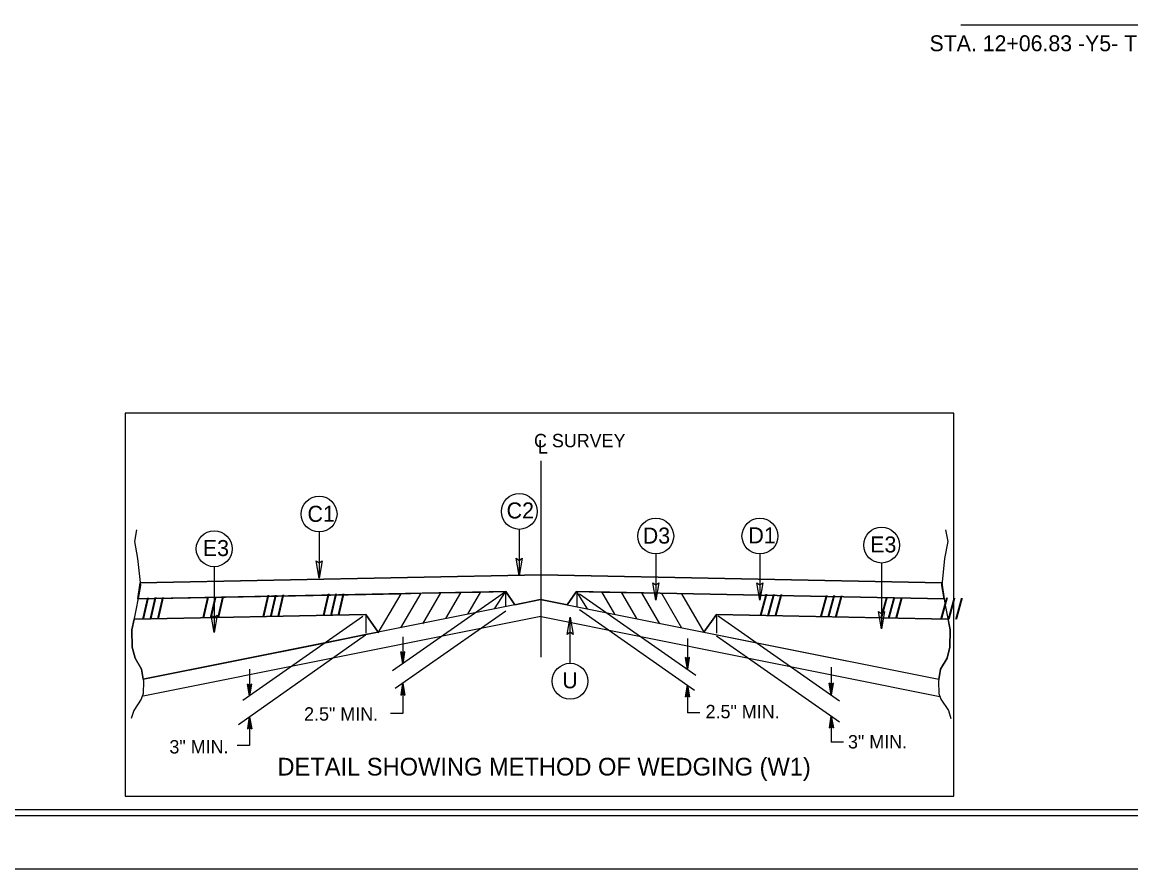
# Model space of a CAD drawing. Extents: x 2176156 to 2177167, y 76401 to 76644.
# Drawn here: x 2176720.1 to 2176795, y 76454.5 to 76511.6 of the extents above; entities that cross this region are included whole.
import ezdxf

# ---------------------------------------------------------------- set-up
doc = ezdxf.new("R2010")
doc.units = 0
for name, color, linetype in [('Exist Other Culture Fence Line', 7, 'Continuous'), ('Exist Utilities Water Fire Hydrant CELL', 7, 'Continuous'), ('Exist Vegetation Hedge Row', 7, 'Continuous'), ('Exist Vegetation Shrub CELL', 7, 'Continuous'), ('Exist Vegetation Woods Line', 7, 'Continuous'), ('Model Boundary Lines', 7, 'Continuous'), ('Model Boundary Lines Text', 7, 'Continuous'), ('Old_Level_1', 7, 'Continuous'), ('Prop North Arrow NAD83 for Plan Sheets CELL', 7, 'Continuous'), ('Scratch_Level_0', 7, 'Continuous'), ('Sheet Cutting Line CELL', 7, 'Continuous'), ('Sheet Data Field CELL', 7, 'Continuous'), ('Sheet Plot Border Outside CELL', 7, 'Continuous'), ('Sheet Sticker Exception Certification CELL', 7, 'Continuous')]:
    doc.layers.add(name, color=color, linetype=linetype)

msp = doc.modelspace()

# ---------------------------------------------------------------- linework, layer by layer
at = {"layer": 'Exist Other Culture Fence Line'}
msp.add_lwpolyline([(2176727.086, 76459.386), (2176783.012, 76459.386), (2176783.012, 76485.213), (2176727.086, 76485.213)], close=True, dxfattribs=at)
at = {"layer": 'Exist Utilities Water Fire Hydrant CELL'}
for p, q in [((2176727.938, 76472.689), (2176728.092, 76473.776)), ((2176755.147, 76474.316), (2176728.092, 76473.776)), ((2176728.092, 76473.776), (2176755.147, 76474.316)), ((2176755.147, 76474.316), (2176782.204, 76473.776)), ((2176755.15, 76474.316), (2176782.204, 76473.776)), ((2176782.204, 76473.776), (2176782.36, 76472.689)), ((2176752.774, 76473.185), (2176727.938, 76472.689)), ((2176752.774, 76473.185), (2176727.938, 76472.689)), ((2176745.679, 76473.043), (2176744.141, 76470.408)), ((2176752.743, 76473.165), (2176745.121, 76467.826)), ((2176747.028, 76473.071), (2176745.668, 76470.734)), ((2176748.365, 76473.097), (2176747.144, 76471.003)), ((2176749.712, 76473.094), (2176748.699, 76471.36)), ((2176751.069, 76473.163), (2176750.187, 76471.65)), ((2176752.005, 76472.028), (2176752.739, 76473.175)), ((2176752.739, 76473.175), (2176752.739, 76472.232)), ((2176753.382, 76472.294), (2176752.774, 76473.185)), ((2176752.774, 76473.156), (2176753.382, 76472.294)), ((2176757.541, 76473.185), (2176756.914, 76472.294)), ((2176757.541, 76473.185), (2176756.914, 76472.294)), ((2176757.502, 76473.165), (2176757.54, 76473.163)), ((2176757.541, 76473.185), (2176782.36, 76472.689)), ((2176782.36, 76472.689), (2176757.541, 76473.185)), ((2176758.291, 76472.028), (2176757.557, 76473.175)), ((2176757.557, 76473.175), (2176757.557, 76472.137)), ((2176757.748, 76473.041), (2176765.602, 76467.541)), ((2176759.226, 76473.163), (2176760.11, 76471.65)), ((2176760.584, 76473.094), (2176761.597, 76471.36)), ((2176761.931, 76473.097), (2176763.153, 76471.003)), ((2176763.268, 76473.071), (2176764.629, 76470.734)), ((2176764.619, 76473.043), (2176766.133, 76470.447)), ((2176755.188, 76472.653), (2176728.295, 76467.273)), ((2176755.108, 76472.653), (2176753.382, 76472.294)), ((2176755.108, 76472.653), (2176782.001, 76467.273)), ((2176756.914, 76472.294), (2176755.108, 76472.653)), ((2176743.312, 76471.639), (2176727.675, 76471.326)), ((2176727.675, 76471.326), (2176743.312, 76471.639)), ((2176755.137, 76471.495), (2176728.286, 76466.124)), ((2176743.128, 76471.51), (2176735.009, 76465.825)), ((2176744.163, 76470.444), (2176743.312, 76471.639)), ((2176743.312, 76471.639), (2176743.312, 76470.377)), ((2176743.312, 76471.639), (2176744.161, 76470.447)), ((2176752.761, 76471.86), (2176745.302, 76466.638)), ((2176755.158, 76471.495), (2176782.072, 76466.111)), ((2176757.737, 76471.972), (2176765.514, 76466.527)), ((2176766.984, 76471.639), (2176766.133, 76470.447)), ((2176766.135, 76470.447), (2176766.984, 76471.639)), ((2176766.984, 76471.639), (2176782.622, 76471.326)), ((2176766.984, 76471.639), (2176766.984, 76470.371)), ((2176778.136, 76471.416), (2176766.984, 76471.639)), ((2176767.11, 76471.551), (2176775.3, 76465.816)), ((2176782.622, 76471.326), (2176778.136, 76471.416)), ((2176743.305, 76470.232), (2176734.722, 76464.192)), ((2176743.312, 76470.277), (2176740.589, 76469.732)), ((2176744.161, 76470.447), (2176743.312, 76470.277)), ((2176745.815, 76470.127), (2176745.815, 76468.313)), ((2176765.028, 76470.022), (2176765.028, 76467.943)), ((2176766.133, 76470.447), (2176769.708, 76469.732)), ((2176766.984, 76470.206), (2176775.286, 76464.391)), ((2176740.589, 76469.732), (2176728.295, 76467.273)), ((2176769.708, 76469.732), (2176782.001, 76467.273)), ((2176745.815, 76468.313), (2176745.674, 76469.108)), ((2176745.815, 76469.005), (2176745.674, 76469.108)), ((2176745.815, 76468.313), (2176745.694, 76469.093)), ((2176745.714, 76469.078), (2176745.815, 76468.313)), ((2176745.815, 76468.313), (2176745.734, 76469.064)), ((2176745.755, 76469.049), (2176745.815, 76468.313)), ((2176745.815, 76468.313), (2176745.775, 76469.035)), ((2176745.795, 76469.02), (2176745.815, 76468.313)), ((2176745.815, 76468.313), (2176745.956, 76469.108)), ((2176745.956, 76469.108), (2176745.815, 76469.005)), ((2176745.936, 76469.093), (2176745.815, 76468.313)), ((2176745.815, 76468.313), (2176745.914, 76469.078)), ((2176745.894, 76469.064), (2176745.815, 76468.313)), ((2176745.815, 76468.313), (2176745.874, 76469.049)), ((2176745.855, 76469.035), (2176745.815, 76468.313)), ((2176745.815, 76468.313), (2176745.835, 76469.02)), ((2176745.815, 76469.005), (2176745.815, 76468.313)), ((2176765.028, 76467.943), (2176764.888, 76468.739)), ((2176765.028, 76468.636), (2176764.888, 76468.739)), ((2176765.028, 76467.943), (2176764.908, 76468.724)), ((2176764.928, 76468.709), (2176765.028, 76467.943)), ((2176765.028, 76467.943), (2176764.948, 76468.694)), ((2176764.967, 76468.679), (2176765.028, 76467.943)), ((2176765.028, 76467.943), (2176764.987, 76468.666)), ((2176765.007, 76468.651), (2176765.028, 76467.943)), ((2176765.028, 76467.943), (2176765.168, 76468.739)), ((2176765.168, 76468.739), (2176765.028, 76468.636)), ((2176765.147, 76468.724), (2176765.028, 76467.943)), ((2176765.028, 76467.943), (2176765.128, 76468.709)), ((2176765.108, 76468.694), (2176765.028, 76467.943)), ((2176765.028, 76467.943), (2176765.088, 76468.679)), ((2176765.068, 76468.666), (2176765.028, 76467.943)), ((2176765.028, 76467.943), (2176765.048, 76468.651)), ((2176765.028, 76468.636), (2176765.028, 76467.943)), ((2176735.477, 76467.959), (2176735.477, 76466.151)), ((2176774.737, 76468.091), (2176774.737, 76466.211)), ((2176735.477, 76466.151), (2176735.335, 76466.947)), ((2176735.477, 76466.844), (2176735.335, 76466.947)), ((2176735.477, 76466.151), (2176735.355, 76466.933)), ((2176735.377, 76466.917), (2176735.477, 76466.151)), ((2176735.477, 76466.151), (2176735.397, 76466.903)), ((2176735.477, 76466.151), (2176735.617, 76466.947)), ((2176735.617, 76466.947), (2176735.477, 76466.844)), ((2176735.597, 76466.933), (2176735.477, 76466.151)), ((2176735.477, 76466.151), (2176735.577, 76466.917)), ((2176735.557, 76466.903), (2176735.477, 76466.151)), ((2176745.815, 76466.997), (2176745.674, 76466.201)), ((2176745.694, 76466.217), (2176745.815, 76466.997)), ((2176745.815, 76466.997), (2176745.714, 76466.231)), ((2176745.734, 76466.247), (2176745.815, 76466.997)), ((2176745.815, 76466.997), (2176745.755, 76466.261)), ((2176745.775, 76466.274), (2176745.815, 76466.997)), ((2176745.815, 76466.997), (2176745.795, 76466.289)), ((2176745.815, 76466.997), (2176745.815, 76464.955)), ((2176745.815, 76466.997), (2176745.956, 76466.201)), ((2176745.815, 76466.304), (2176745.815, 76466.997)), ((2176745.835, 76466.289), (2176745.815, 76466.997)), ((2176745.815, 76466.997), (2176745.855, 76466.274)), ((2176745.874, 76466.261), (2176745.815, 76466.997)), ((2176745.815, 76466.997), (2176745.894, 76466.247)), ((2176745.914, 76466.231), (2176745.815, 76466.997)), ((2176745.815, 76466.997), (2176745.936, 76466.217)), ((2176774.737, 76466.211), (2176774.596, 76467.006)), ((2176774.737, 76466.903), (2176774.596, 76467.006)), ((2176774.737, 76466.211), (2176774.616, 76466.991)), ((2176774.636, 76466.977), (2176774.737, 76466.211)), ((2176774.737, 76466.211), (2176774.656, 76466.963)), ((2176774.676, 76466.947), (2176774.737, 76466.211)), ((2176774.737, 76466.211), (2176774.696, 76466.933)), ((2176774.716, 76466.917), (2176774.737, 76466.211)), ((2176774.737, 76466.211), (2176774.877, 76467.006)), ((2176774.877, 76467.006), (2176774.737, 76466.903)), ((2176774.856, 76466.991), (2176774.737, 76466.211)), ((2176774.737, 76466.211), (2176774.836, 76466.977)), ((2176774.816, 76466.963), (2176774.737, 76466.211)), ((2176774.737, 76466.211), (2176774.796, 76466.947)), ((2176774.776, 76466.933), (2176774.737, 76466.211)), ((2176774.737, 76466.211), (2176774.757, 76466.917)), ((2176774.737, 76466.903), (2176774.737, 76466.211)), ((2176735.417, 76466.889), (2176735.477, 76466.151)), ((2176735.477, 76466.151), (2176735.437, 76466.874)), ((2176735.457, 76466.859), (2176735.477, 76466.151)), ((2176735.477, 76466.151), (2176735.536, 76466.889)), ((2176735.517, 76466.874), (2176735.477, 76466.151)), ((2176735.477, 76466.151), (2176735.496, 76466.859)), ((2176735.477, 76466.844), (2176735.477, 76466.151)), ((2176745.674, 76466.201), (2176745.815, 76466.304)), ((2176745.815, 76466.304), (2176745.956, 76466.201)), ((2176765.028, 76466.867), (2176764.888, 76466.072)), ((2176764.888, 76466.072), (2176765.028, 76466.175)), ((2176764.908, 76466.087), (2176765.028, 76466.867)), ((2176765.028, 76466.867), (2176764.928, 76466.101)), ((2176764.948, 76466.117), (2176765.028, 76466.867)), ((2176765.028, 76466.867), (2176764.967, 76466.131)), ((2176764.987, 76466.145), (2176765.028, 76466.867)), ((2176765.028, 76466.867), (2176765.007, 76466.16)), ((2176765.028, 76466.867), (2176765.028, 76465.007)), ((2176765.028, 76466.867), (2176765.168, 76466.072)), ((2176765.028, 76466.175), (2176765.028, 76466.867)), ((2176765.048, 76466.16), (2176765.028, 76466.867)), ((2176765.028, 76466.867), (2176765.068, 76466.145)), ((2176765.088, 76466.131), (2176765.028, 76466.867)), ((2176765.028, 76466.867), (2176765.108, 76466.117)), ((2176765.128, 76466.101), (2176765.028, 76466.867)), ((2176765.028, 76466.867), (2176765.147, 76466.087)), ((2176765.028, 76466.175), (2176765.168, 76466.072)), ((2176735.477, 76464.721), (2176735.335, 76463.925)), ((2176735.357, 76463.94), (2176735.477, 76464.721)), ((2176735.477, 76464.721), (2176735.377, 76463.955)), ((2176735.397, 76463.97), (2176735.477, 76464.721)), ((2176735.477, 76464.721), (2176735.417, 76463.985)), ((2176735.437, 76463.999), (2176735.477, 76464.721)), ((2176735.477, 76464.721), (2176735.457, 76464.013)), ((2176735.477, 76464.721), (2176735.477, 76462.787)), ((2176735.477, 76464.721), (2176735.617, 76463.925)), ((2176735.477, 76464.029), (2176735.477, 76464.721)), ((2176735.496, 76464.013), (2176735.477, 76464.721)), ((2176735.477, 76464.721), (2176735.517, 76463.999)), ((2176735.537, 76463.985), (2176735.477, 76464.721)), ((2176735.477, 76464.721), (2176735.557, 76463.97)), ((2176735.577, 76463.955), (2176735.477, 76464.721)), ((2176735.477, 76464.721), (2176735.597, 76463.94)), ((2176745.815, 76464.955), (2176744.98, 76464.955)), ((2176765.863, 76465.007), (2176765.028, 76465.007)), ((2176774.737, 76464.777), (2176774.596, 76463.981)), ((2176774.616, 76463.996), (2176774.737, 76464.777)), ((2176774.737, 76464.777), (2176774.636, 76464.011)), ((2176774.656, 76464.026), (2176774.737, 76464.777)), ((2176774.737, 76464.777), (2176774.676, 76464.04)), ((2176774.696, 76464.055), (2176774.737, 76464.777)), ((2176774.737, 76464.777), (2176774.716, 76464.069)), ((2176774.737, 76464.777), (2176774.737, 76463.03)), ((2176774.737, 76464.777), (2176774.877, 76463.981)), ((2176774.737, 76464.085), (2176774.737, 76464.777)), ((2176774.757, 76464.069), (2176774.737, 76464.777)), ((2176774.737, 76464.777), (2176774.776, 76464.055)), ((2176774.796, 76464.04), (2176774.737, 76464.777)), ((2176774.737, 76464.777), (2176774.816, 76464.026)), ((2176774.836, 76464.011), (2176774.737, 76464.777)), ((2176774.737, 76464.777), (2176774.856, 76463.996)), ((2176735.335, 76463.925), (2176735.477, 76464.029)), ((2176735.477, 76464.029), (2176735.617, 76463.925)), ((2176774.596, 76463.981), (2176774.737, 76464.085)), ((2176774.737, 76464.085), (2176774.877, 76463.981)), ((2176735.477, 76462.787), (2176734.642, 76462.787)), ((2176775.571, 76463.03), (2176774.737, 76463.03))]:
    msp.add_line(p, q, dxfattribs=at)
for points in [[(2176727.841, 76477.347), (2176727.697, 76476.554), (2176727.913, 76475.427), (2176728.104, 76473.603), (2176727.841, 76472.163), (2176727.529, 76470.603), (2176727.553, 76469.426), (2176727.745, 76468.683), (2176728.178, 76467.938), (2176728.321, 76467.123), (2176728.297, 76466.307), (2176728.153, 76465.922), (2176727.65, 76465.154), (2176727.482, 76464.626)], [(2176782.455, 76477.347), (2176782.599, 76476.554), (2176782.383, 76475.427), (2176782.191, 76473.603), (2176782.455, 76472.163), (2176782.767, 76470.603), (2176782.743, 76469.426), (2176782.551, 76468.683), (2176782.119, 76467.938), (2176781.976, 76467.123), (2176781.998, 76466.307), (2176782.143, 76465.922), (2176782.646, 76465.154), (2176782.814, 76464.626)], [(2176728.294, 76467.273), (2176728.178, 76467.938), (2176727.745, 76468.683), (2176727.553, 76469.426), (2176727.529, 76470.603), (2176727.674, 76471.326)], [(2176782.001, 76467.273), (2176782.119, 76467.938), (2176782.551, 76468.683), (2176782.743, 76469.426), (2176782.767, 76470.603), (2176782.622, 76471.326)]]:
    msp.add_lwpolyline(points, dxfattribs=at)
at = {"layer": 'Exist Vegetation Shrub CELL'}
for p, q in [((2176753.679, 76477.383), (2176753.679, 76474.26)), ((2176740.167, 76477.209), (2176740.167, 76474.086)), ((2176762.891, 76475.723), (2176762.891, 76472.6)), ((2176769.92, 76475.723), (2176769.92, 76472.6)), ((2176733.084, 76474.863), (2176733.084, 76470.422)), ((2176778.136, 76475.111), (2176778.136, 76470.67)), ((2176757.106, 76468.345), (2176757.106, 76471.468))]:
    msp.add_line(p, q, dxfattribs=at)
for centre in [(2176740.167, 76478.418), (2176753.679, 76478.592), (2176762.891, 76476.932), (2176769.919, 76476.932), (2176778.136, 76476.319), (2176733.084, 76476.071), (2176757.106, 76467.137)]:
    msp.add_circle(centre, 1.208, dxfattribs=at)
at = {"layer": 'Model Boundary Lines Text'}
msp.add_line((2176783.485, 76511.423), (2176810.807, 76511.423), dxfattribs=at)
at = {"layer": 'Old_Level_1'}
for points in [[(2176740.369, 76475.258), (2176740.167, 76474.086), (2176739.959, 76475.264), (2176740.167, 76475.115)], [(2176740.369, 76475.258), (2176740.167, 76474.086), (2176739.959, 76475.264), (2176740.167, 76475.115)], [(2176753.881, 76475.432), (2176753.679, 76474.26), (2176753.471, 76475.439), (2176753.679, 76475.289)], [(2176753.881, 76475.432), (2176753.679, 76474.26), (2176753.471, 76475.439), (2176753.679, 76475.289)], [(2176763.092, 76473.772), (2176762.891, 76472.6), (2176762.682, 76473.779), (2176762.891, 76473.629)], [(2176763.092, 76473.772), (2176762.891, 76472.6), (2176762.682, 76473.779), (2176762.891, 76473.629)], [(2176770.121, 76473.772), (2176769.92, 76472.6), (2176769.711, 76473.779), (2176769.92, 76473.629)], [(2176770.121, 76473.772), (2176769.92, 76472.6), (2176769.711, 76473.779), (2176769.92, 76473.629)], [(2176733.286, 76471.594), (2176733.084, 76470.422), (2176732.876, 76471.6), (2176733.084, 76471.451)], [(2176733.286, 76471.594), (2176733.084, 76470.422), (2176732.876, 76471.6), (2176733.084, 76471.451)], [(2176756.904, 76470.297), (2176757.106, 76471.468), (2176757.314, 76470.29), (2176757.106, 76470.44)], [(2176756.904, 76470.297), (2176757.106, 76471.468), (2176757.314, 76470.29), (2176757.106, 76470.44)], [(2176778.338, 76471.841), (2176778.136, 76470.67), (2176777.928, 76471.848), (2176778.136, 76471.698)]]:
    msp.add_lwpolyline(points, close=True, dxfattribs=at)
at = {"layer": 'Prop North Arrow NAD83 for Plan Sheets CELL'}
for p, q in [((2176755.148, 76468.754), (2176755.148, 76482.012)), ((2176728.092, 76473.776), (2176728.089, 76473.751)), ((2176755.147, 76474.316), (2176728.092, 76473.776)), ((2176782.207, 76473.755), (2176782.204, 76473.776)), ((2176727.938, 76472.689), (2176745.679, 76473.043)), ((2176745.679, 76473.043), (2176747.028, 76473.07)), ((2176747.028, 76473.07), (2176747.028, 76473.071)), ((2176752.774, 76473.185), (2176753.382, 76472.294)), ((2176757.541, 76473.185), (2176759.233, 76473.151)), ((2176763.268, 76473.071), (2176763.268, 76473.071)), ((2176763.268, 76473.071), (2176764.619, 76473.044)), ((2176764.619, 76473.044), (2176782.359, 76472.689)), ((2176727.942, 76472.718), (2176727.938, 76472.689)), ((2176753.382, 76472.294), (2176755.108, 76472.653)), ((2176743.312, 76471.639), (2176727.675, 76471.326)), ((2176744.161, 76470.447), (2176743.312, 76471.639)), ((2176766.984, 76471.639), (2176766.133, 76470.447)), ((2176778.136, 76471.416), (2176766.984, 76471.639)), ((2176782.622, 76471.326), (2176778.136, 76471.416)), ((2176727.675, 76471.326), (2176727.529, 76470.603)), ((2176769.708, 76469.732), (2176782.001, 76467.273)), ((2176782.119, 76467.938), (2176782.551, 76468.683)), ((2176728.178, 76467.938), (2176728.295, 76467.273)), ((2176782.001, 76467.273), (2176782.119, 76467.938))]:
    msp.add_line(p, q, dxfattribs=at)
for points in [[(2176728.089, 76473.751), (2176728.104, 76473.603), (2176727.942, 76472.718)], [(2176782.204, 76473.776), (2176755.15, 76474.316), (2176755.147, 76474.316)], [(2176782.359, 76472.689), (2176782.191, 76473.603), (2176782.207, 76473.755)], [(2176747.028, 76473.07), (2176748.365, 76473.097), (2176751.062, 76473.151), (2176752.774, 76473.185)], [(2176747.028, 76473.071), (2176747.028, 76473.07)], [(2176756.914, 76472.294), (2176757.527, 76473.164), (2176757.541, 76473.185)], [(2176759.233, 76473.151), (2176761.931, 76473.097), (2176763.268, 76473.071)], [(2176763.268, 76473.071), (2176763.268, 76473.071)], [(2176755.108, 76472.653), (2176755.148, 76472.645), (2176756.914, 76472.294)], [(2176782.551, 76468.683), (2176782.743, 76469.426), (2176782.767, 76470.603), (2176782.622, 76471.326)], [(2176727.529, 76470.603), (2176727.553, 76469.426), (2176727.745, 76468.683), (2176728.178, 76467.938)], [(2176728.295, 76467.273), (2176740.589, 76469.732), (2176740.589, 76469.732), (2176743.312, 76470.277)], [(2176743.312, 76470.277), (2176744.118, 76470.438), (2176744.161, 76470.447)], [(2176766.133, 76470.447), (2176769.707, 76469.733), (2176769.708, 76469.732)]]:
    msp.add_lwpolyline(points, dxfattribs=at)
at = {"layer": 'Sheet Cutting Line CELL'}
msp.add_lwpolyline([(2176898.707, 76630.475), (2176629.267, 76630.475), (2176629.267, 76454.475), (2176898.707, 76454.475)], close=True, dxfattribs=at)
at = {"layer": 'Sheet Data Field CELL'}
msp.add_lwpolyline([(2176895.987, 76626.475), (2176655.987, 76626.475), (2176655.987, 76458.475), (2176895.987, 76458.475)], close=True, dxfattribs=at)
at = {"layer": 'Sheet Plot Border Outside CELL'}
msp.add_lwpolyline([(2176897.987, 76626.883), (2176631.347, 76626.883), (2176631.347, 76458.067), (2176897.987, 76458.067)], close=True, dxfattribs=at)
at = {"layer": 'Sheet Sticker Exception Certification CELL'}
msp.add_line((2176629.267, 76454.475), (2176898.707, 76454.475), dxfattribs=at)

# ---------------------------------------------------------------- texts
at = {"layer": 'Exist Utilities Water Fire Hydrant CELL'}
for height, rotation, p in [(1.3562, 1.14453, (2176736.332, 76471.512)), (1.3563, 1.14629, (2176740.4, 76471.596)), (1.3563, 358.85527, (2176769.897, 76471.596)), (1.3562, 358.85361, (2176773.965, 76471.512)), (1.3568, 1.14473, (2176728.213, 76471.345)), (1.3568, 1.14639, (2176732.268, 76471.393)), (1.3568, 358.85537, (2176778.028, 76471.393)), (1.3568, 358.85371, (2176782.083, 76471.345))]:
    msp.add_text('/// ', height=height, rotation=rotation, dxfattribs=at).set_placement(p)
for s, p in [('2.5" MIN.', (2176766.253, 76464.634)), ('2.5" MIN.', (2176739.153, 76464.473)), ('3" MIN.', (2176730.062, 76462.258)), ('3" MIN.', (2176775.866, 76462.598))]:
    msp.add_text(s, height=0.9039, dxfattribs=at).set_placement(p)
at = {"layer": 'Exist Vegetation Hedge Row'}
for s, height, p in [('C1', 1.0817, (2176739.381, 76477.891)), ('C2', 1.0817, (2176752.82, 76478.118)), ('D3', 1.0817, (2176762.012, 76476.421)), ('D1', 1.0817, (2176769.142, 76476.439)), ('E3', 1.0817, (2176732.315, 76475.58)), ('E3', 1.0817, (2176777.363, 76475.825)), ('U', 1.082, (2176756.578, 76466.658))]:
    msp.add_text(s, height=height, dxfattribs=at).set_placement(p)
at = {"layer": 'Exist Vegetation Woods Line'}
msp.add_text('STA. 12+06.83 -Y5- TO STA. 23+00.00 -Y5-', height=1.0742, dxfattribs=at).set_placement((2176781.369, 76509.649))
at = {"layer": 'Model Boundary Lines'}
msp.add_text('DETAIL SHOWING METHOD OF WEDGING (W1)', height=1.19356, dxfattribs=at).set_placement((2176737.355, 76460.772))
at = {"layer": 'Scratch_Level_0'}
for s, height, p in [('C SURVEY ', 0.9039, (2176754.67, 76482.922)), ('L', 0.904, (2176754.935, 76482.499))]:
    msp.add_text(s, height=height, dxfattribs=at).set_placement(p)

doc.saveas('drawing.dxf')
